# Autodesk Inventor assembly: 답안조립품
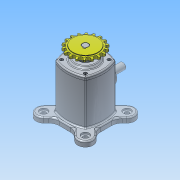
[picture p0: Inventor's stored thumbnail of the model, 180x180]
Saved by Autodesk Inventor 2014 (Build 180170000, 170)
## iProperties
Created: 2016-05
Part Number: 답안조립품
Document SubType Name: Assembly
Designer: net
Author: net
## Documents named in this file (11)
- C:\Users\net\Desktop\460507V1005\답안조립품.iam
- C:\Users\net\Desktop\460507V1005\M4x0.7x12.ipt
- C:\Users\net\Desktop\460507V1005\답안도면.ipt
- C:\Users\net\Desktop\460507V1005\베어링-6203.ipt
- C:\Users\net\Desktop\460507V1005\부시.ipt
- C:\Users\net\Desktop\460507V1005\스프로킷.ipt
- C:\Users\net\Desktop\460507V1005\슬라이더.ipt
- C:\Users\net\Desktop\460507V1005\오일실.ipt
- C:\Users\net\Desktop\460507V1005\커버.ipt
- C:\Users\net\Desktop\460507V1005\키5x5.ipt
- C:\Users\net\Desktop\460507V1005\편심축.ipt
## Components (8 placed, 1 different names)
1. M4x0.7x12:1
2. M4x0.7x12:3
3. M4x0.7x12:4
4. M4x0.7x12:5
5. M4x0.7x12:2
6. M4x0.7x12:6
7. M4x0.7x12:7
8. M4x0.7x12:8
